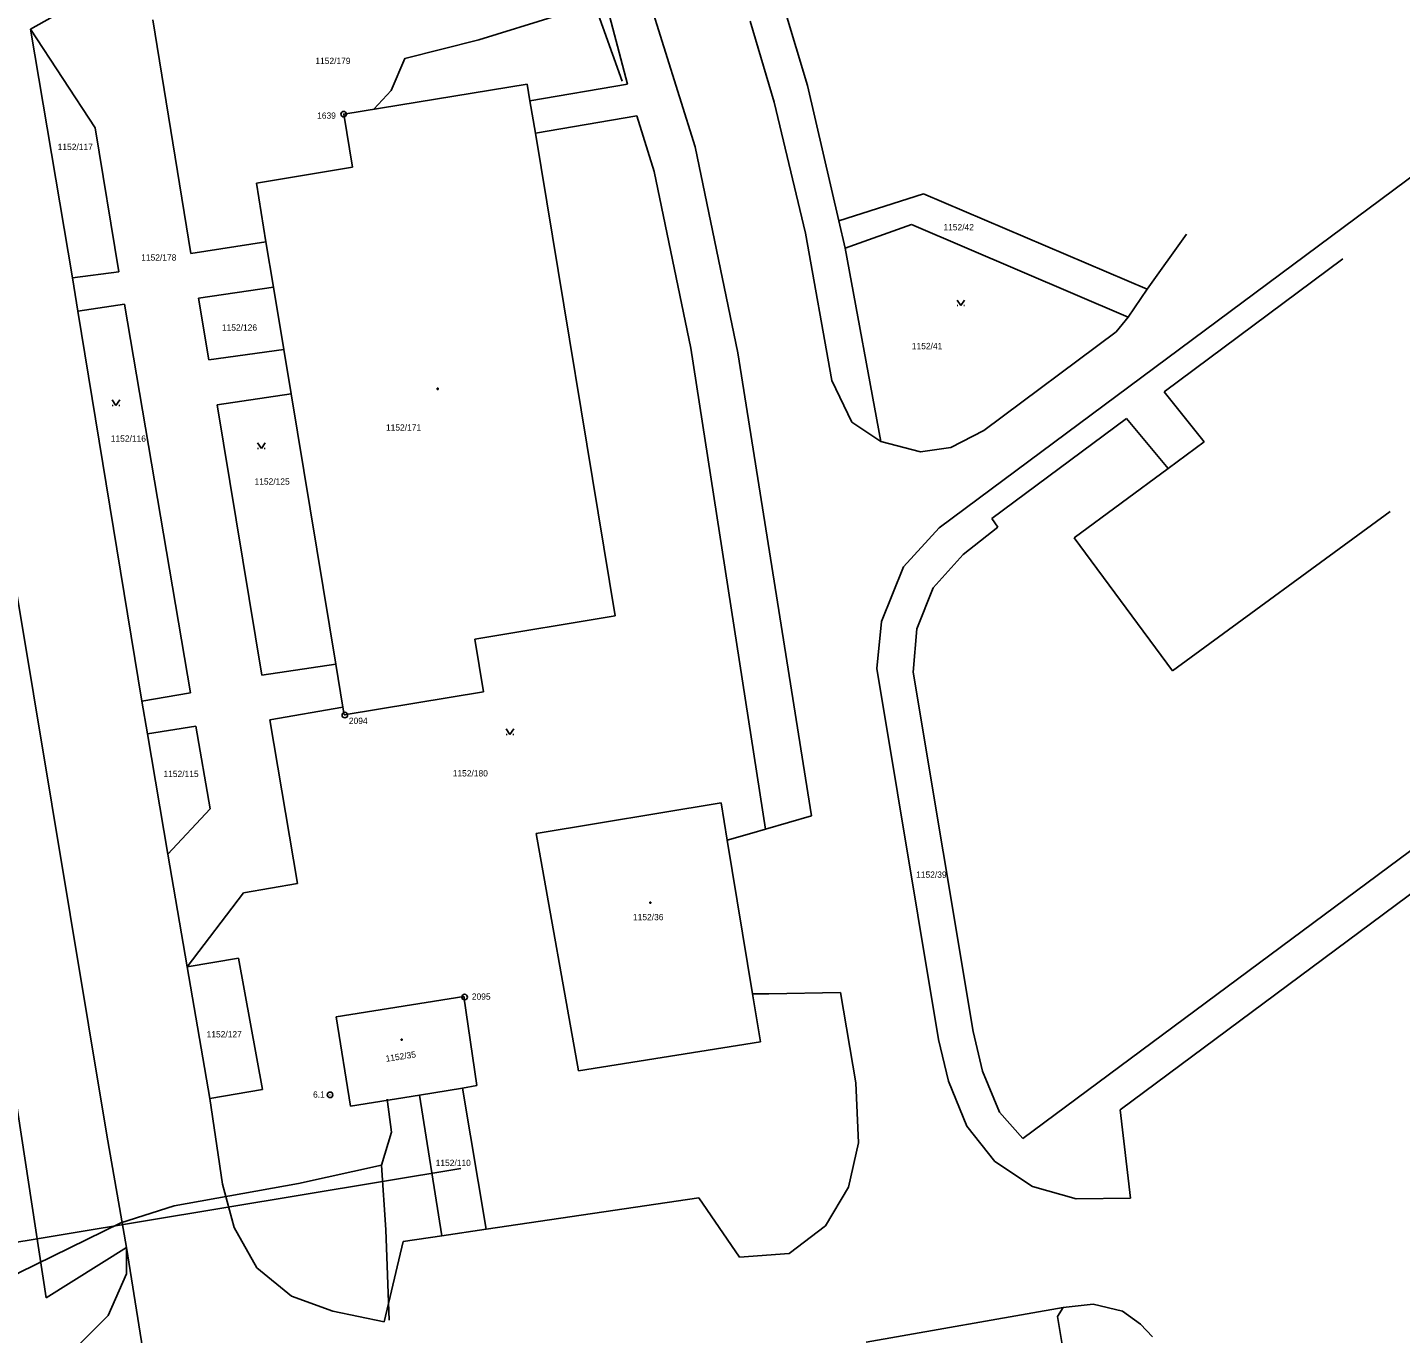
# Model space of a CAD drawing. Extents: x -609709 to -609357, y -1051535 to -1051131.
# Drawn here: x -609496.9 to -609404.3, y -1051388.6 to -1051300.6 of the extents above; entities that cross this region are included whole.
import ezdxf

# ---------------------------------------------------------------- set-up
doc = ezdxf.new("R2010")
doc.units = 0
for name, color, linetype in [('Vrstva 10', 7, 'Continuous'), ('Vrstva 12', 7, 'Continuous'), ('Vrstva 15', 7, 'Continuous')]:
    doc.layers.add(name, color=color, linetype=linetype)

msp = doc.modelspace()

# ---------------------------------------------------------------- linework, layer by layer
at = {"layer": 'Vrstva 10'}
for p, q in [((-609432.83, -1051332.32), (-609357.01, -1051275.97)), ((-609458.85, -1051295.32), (-609456.45, -1051304.37)), ((-609496.71, -1051300.67), (-609492.16, -1051298.11)), ((-609455.21, -1051298.05), (-609451.89, -1051308.61)), ((-609445.86, -1051299.39), (-609444.32, -1051304.46)), ((-609488.45, -1051300.05), (-609485.89, -1051315.79)), ((-609448.19, -1051300.13), (-609446.56, -1051305.59)), ((-609496.71, -1051300.67), (-609492.35, -1051307.31)), ((-609496.71, -1051300.67), (-609493.88, -1051317.44)), ((-609475.59, -1051306.4), (-609463.22, -1051304.37)), ((-609463.22, -1051304.37), (-609463.04, -1051305.49)), ((-609463.04, -1051305.49), (-609456.45, -1051304.37)), ((-609444.32, -1051304.46), (-609442.21, -1051313.59)), ((-609463.04, -1051305.49), (-609462.67, -1051307.68)), ((-609446.56, -1051305.59), (-609444.46, -1051314.42)), ((-609475.59, -1051306.4), (-609474.99, -1051309.98)), ((-609462.67, -1051307.68), (-609455.83, -1051306.52)), ((-609455.83, -1051306.52), (-609454.65, -1051310.27)), ((-609492.35, -1051307.31), (-609490.75, -1051317.02)), ((-609462.67, -1051307.68), (-609457.3, -1051340.22)), ((-609451.89, -1051308.61), (-609449.03, -1051322.49)), ((-609462.37, -1051309.5), (-609462.37, -1051309.5)), ((-609481.47, -1051311.06), (-609474.99, -1051309.98)), ((-609454.65, -1051310.27), (-609452.19, -1051322.16)), ((-609481.47, -1051311.06), (-609480.83, -1051315.01)), ((-609454.28, -1051312.05), (-609454.28, -1051312.05)), ((-609442.21, -1051313.59), (-609436.51, -1051311.76)), ((-609436.51, -1051311.76), (-609421.42, -1051318.19)), ((-609453.88, -1051314.01), (-609453.88, -1051314.01)), ((-609442.21, -1051313.59), (-609441.79, -1051315.42)), ((-609441.79, -1051315.42), (-609437.31, -1051313.84)), ((-609437.31, -1051313.84), (-609422.7, -1051320.08)), ((-609485.89, -1051315.79), (-609480.83, -1051315.01)), ((-609480.83, -1051315.01), (-609480.32, -1051318.07)), ((-609444.46, -1051314.42), (-609442.68, -1051324.36)), ((-609421.42, -1051318.19), (-609418.77, -1051314.48)), ((-609441.79, -1051315.42), (-609439.38, -1051328.47)), ((-609420.29, -1051325.11), (-609408.23, -1051316.16)), ((-609493.88, -1051317.44), (-609490.75, -1051317.02)), ((-609493.88, -1051317.44), (-609493.51, -1051319.67)), ((-609485.37, -1051318.79), (-609480.32, -1051318.07)), ((-609480.32, -1051318.07), (-609479.63, -1051322.26)), ((-609485.37, -1051318.79), (-609484.67, -1051322.95)), ((-609434.23, -1051318.925), (-609433.98, -1051319.3)), ((-609433.98, -1051319.3), (-609433.73, -1051318.925)), ((-609422.7, -1051320.08), (-609421.42, -1051318.19)), ((-609493.51, -1051319.67), (-609490.37, -1051319.21)), ((-609493.51, -1051319.67), (-609489.19, -1051345.96)), ((-609490.37, -1051319.21), (-609485.92, -1051345.41)), ((-609434.23, -1051319.3), (-609434.18, -1051319.3)), ((-609433.78, -1051319.3), (-609433.73, -1051319.3)), ((-609505.79, -1051320.08), (-609495.64, -1051386.18)), ((-609423.51, -1051321.08), (-609422.7, -1051320.08)), ((-609432.44, -1051327.72), (-609423.51, -1051321.08)), ((-609500.39, -1051322.14), (-609491.56, -1051375.22)), ((-609484.67, -1051322.95), (-609479.63, -1051322.26)), ((-609479.63, -1051322.26), (-609479.14, -1051325.24)), ((-609452.19, -1051322.16), (-609447.16, -1051354.59)), ((-609449.03, -1051322.49), (-609444.06, -1051353.69)), ((-609442.68, -1051324.36), (-609441.33, -1051327.15)), ((-609484.13, -1051325.98), (-609479.14, -1051325.24)), ((-609479.14, -1051325.24), (-609476.12, -1051343.46)), ((-609469.295, -1051324.875), (-609469.22, -1051324.875)), ((-609469.295, -1051324.95), (-609469.295, -1051324.875)), ((-609469.22, -1051324.95), (-609469.295, -1051324.95)), ((-609469.22, -1051324.875), (-609469.22, -1051324.95)), ((-609420.29, -1051325.11), (-609417.58, -1051328.48)), ((-609491.19, -1051325.655), (-609490.94, -1051326.03)), ((-609491.19, -1051326.03), (-609491.14, -1051326.03)), ((-609490.94, -1051326.03), (-609490.69, -1051325.655)), ((-609490.74, -1051326.03), (-609490.69, -1051326.03)), ((-609484.13, -1051325.98), (-609481.1, -1051344.21)), ((-609441.33, -1051327.15), (-609439.38, -1051328.47)), ((-609431.9, -1051333.65), (-609422.81, -1051326.91)), ((-609422.81, -1051326.91), (-609420.02, -1051330.28)), ((-609434.66, -1051328.87), (-609432.44, -1051327.72)), ((-609481.39, -1051328.555), (-609481.14, -1051328.93)), ((-609481.39, -1051328.93), (-609481.34, -1051328.93)), ((-609481.14, -1051328.93), (-609480.89, -1051328.555)), ((-609480.94, -1051328.93), (-609480.89, -1051328.93)), ((-609439.38, -1051328.47), (-609436.7, -1051329.15)), ((-609436.7, -1051329.15), (-609434.66, -1051328.87)), ((-609420.02, -1051330.28), (-609417.58, -1051328.48)), ((-609426.34, -1051334.95), (-609420.02, -1051330.28)), ((-609435.44, -1051334.29), (-609432.83, -1051332.32)), ((-609431.9, -1051333.65), (-609431.49, -1051334.23)), ((-609419.71, -1051343.92), (-609405.05, -1051333.17)), ((-609437.86, -1051336.91), (-609435.44, -1051334.29)), ((-609433.83, -1051336.07), (-609431.49, -1051334.23)), ((-609426.34, -1051334.95), (-609419.71, -1051343.92)), ((-609435.85, -1051338.32), (-609433.83, -1051336.07)), ((-609439.34, -1051340.59), (-609437.86, -1051336.91)), ((-609436.96, -1051341.09), (-609435.85, -1051338.32)), ((-609466.75, -1051341.79), (-609457.3, -1051340.22)), ((-609439.66, -1051343.77), (-609439.34, -1051340.59)), ((-609437.2, -1051344.02), (-609436.96, -1051341.09)), ((-609466.75, -1051341.79), (-609466.17, -1051345.34)), ((-609429.8, -1051375.44), (-609383.99, -1051341.41)), ((-609481.1, -1051344.21), (-609476.12, -1051343.46)), ((-609476.12, -1051343.46), (-609475.64, -1051346.37)), ((-609439.66, -1051343.77), (-609435.49, -1051368.77)), ((-609423.24, -1051373.5), (-609382.56, -1051343.27)), ((-609437.2, -1051344.02), (-609433.16, -1051368.24)), ((-609489.19, -1051345.96), (-609485.92, -1051345.41)), ((-609475.56, -1051346.89), (-609466.17, -1051345.34)), ((-609489.19, -1051345.96), (-609488.82, -1051348.17)), ((-609480.56, -1051347.23), (-609475.64, -1051346.37)), ((-609475.64, -1051346.37), (-609475.56, -1051346.89)), ((-609488.82, -1051348.17), (-609485.55, -1051347.65)), ((-609485.55, -1051347.65), (-609484.6, -1051353.23)), ((-609480.56, -1051347.23), (-609478.71, -1051358.25)), ((-609488.82, -1051348.17), (-609487.44, -1051356.28)), ((-609464.63, -1051347.825), (-609464.38, -1051348.2)), ((-609464.63, -1051348.2), (-609464.58, -1051348.2)), ((-609464.38, -1051348.2), (-609464.13, -1051347.825)), ((-609464.18, -1051348.2), (-609464.13, -1051348.2)), ((-609487.44, -1051356.28), (-609484.6, -1051353.23)), ((-609462.61, -1051354.88), (-609450.15, -1051352.81)), ((-609450.15, -1051352.81), (-609449.73, -1051355.34)), ((-609447.16, -1051354.59), (-609444.06, -1051353.69)), ((-609462.61, -1051354.88), (-609459.76, -1051370.89)), ((-609449.73, -1051355.34), (-609448.07, -1051354.86)), ((-609448.07, -1051354.86), (-609447.16, -1051354.59)), ((-609449.73, -1051355.34), (-609448.03, -1051365.7)), ((-609487.44, -1051356.28), (-609486.14, -1051363.88)), ((-609482.35, -1051358.88), (-609478.71, -1051358.25)), ((-609486.14, -1051363.88), (-609482.35, -1051358.88)), ((-609454.955, -1051359.505), (-609454.88, -1051359.505)), ((-609454.955, -1051359.58), (-609454.955, -1051359.505)), ((-609454.88, -1051359.58), (-609454.955, -1051359.58)), ((-609454.88, -1051359.505), (-609454.88, -1051359.58)), ((-609486.14, -1051363.88), (-609482.69, -1051363.29)), ((-609482.69, -1051363.29), (-609481.07, -1051372.14)), ((-609486.14, -1051363.88), (-609484.62, -1051372.75)), ((-609476.09, -1051367.23), (-609467.49, -1051365.86)), ((-609467.49, -1051365.86), (-609466.61, -1051371.88)), ((-609448.03, -1051365.7), (-609446.93, -1051365.68)), ((-609448.03, -1051365.7), (-609447.5, -1051368.92)), ((-609446.93, -1051365.68), (-609442.09, -1051365.6)), ((-609442.09, -1051365.6), (-609441.07, -1051371.69)), ((-609476.09, -1051367.23), (-609475.13, -1051373.26)), ((-609471.72, -1051368.745), (-609471.645, -1051368.745)), ((-609471.72, -1051368.82), (-609471.72, -1051368.745)), ((-609471.645, -1051368.82), (-609471.72, -1051368.82)), ((-609471.645, -1051368.745), (-609471.645, -1051368.82)), ((-609459.76, -1051370.89), (-609447.5, -1051368.92)), ((-609435.49, -1051368.77), (-609434.83, -1051371.58)), ((-609433.16, -1051368.24), (-609432.53, -1051370.9)), ((-609441.07, -1051371.69), (-609440.88, -1051375.74)), ((-609434.83, -1051371.58), (-609433.58, -1051374.6)), ((-609432.53, -1051370.9), (-609431.38, -1051373.66)), ((-609484.62, -1051372.75), (-609481.07, -1051372.14)), ((-609475.13, -1051373.26), (-609470.48, -1051372.51)), ((-609470.48, -1051372.51), (-609467.58, -1051372.04)), ((-609470.48, -1051372.51), (-609468.97, -1051382)), ((-609467.58, -1051372.04), (-609466.61, -1051371.88)), ((-609467.58, -1051372.04), (-609465.99, -1051381.56)), ((-609484.62, -1051372.75), (-609483.77, -1051378.51)), ((-609423.24, -1051373.5), (-609422.55, -1051379.46)), ((-609431.38, -1051373.66), (-609429.8, -1051375.44)), ((-609491.56, -1051375.22), (-609490.24, -1051382.78)), ((-609433.58, -1051374.6), (-609431.7, -1051376.99)), ((-609441.56, -1051378.72), (-609440.88, -1051375.74)), ((-609431.7, -1051376.99), (-609429.15, -1051378.68)), ((-609483.77, -1051378.51), (-609482.98, -1051381.45)), ((-609443.12, -1051381.33), (-609441.56, -1051378.72)), ((-609429.15, -1051378.68), (-609426.21, -1051379.5)), ((-609465.99, -1051381.56), (-609451.66, -1051379.45)), ((-609451.66, -1051379.45), (-609448.91, -1051383.44)), ((-609426.21, -1051379.5), (-609422.55, -1051379.46)), ((-609482.98, -1051381.45), (-609481.45, -1051384.15)), ((-609468.97, -1051382), (-609465.99, -1051381.56)), ((-609445.56, -1051383.19), (-609443.12, -1051381.33)), ((-609495.64, -1051386.18), (-609490.24, -1051382.78)), ((-609490.24, -1051382.78), (-609490.23, -1051384.57)), ((-609490.24, -1051382.78), (-609487.04, -1051402.58)), ((-609472.86, -1051387.81), (-609471.58, -1051382.38)), ((-609471.58, -1051382.38), (-609468.97, -1051382)), ((-609448.91, -1051383.44), (-609445.56, -1051383.19)), ((-609491.46, -1051387.37), (-609490.23, -1051384.57)), ((-609481.45, -1051384.15), (-609479.1, -1051386.08)), ((-609479.1, -1051386.08), (-609476.33, -1051387.08)), ((-609493.63, -1051389.53), (-609491.46, -1051387.37)), ((-609476.33, -1051387.08), (-609472.86, -1051387.81)), ((-609440.36, -1051389.16), (-609427.08, -1051386.84)), ((-609427.08, -1051386.84), (-609427.46, -1051387.44)), ((-609427.46, -1051387.44), (-609426.8, -1051391.39)), ((-609427.08, -1051386.84), (-609425.07, -1051386.6)), ((-609425.07, -1051386.6), (-609423.1, -1051387.07)), ((-609423.1, -1051387.07), (-609421.88, -1051387.95)), ((-609421.88, -1051387.95), (-609421.07, -1051388.81))]:
    msp.add_line(p, q, dxfattribs=at)
for centre, radius in [((-609475.59, -1051306.4), 0.188), ((-609475.59, -1051306.4), 0.0025), ((-609475.51, -1051346.9), 0.188), ((-609475.51, -1051346.9), 0.0025), ((-609467.44, -1051365.91), 0.188), ((-609467.44, -1051365.91), 0.0025), ((-609476.51, -1051372.5), 0.188), ((-609476.51, -1051372.5), 0.0025)]:
    msp.add_circle(centre, radius, dxfattribs=at)
at = {"layer": 'Vrstva 12'}
for points in [[(-609615.546, -1051325.052), (-609614.108, -1051326.974), (-609589.099, -1051308.266), (-609582.815, -1051303.565), (-609514.844, -1051393.856), (-609499.807, -1051382.785), (-609467.693, -1051377.467)], [(-609513.99, -1051396.17), (-609509.03, -1051392.84), (-609504.6, -1051389.36), (-609497.48, -1051384.5), (-609490.61, -1051381.13), (-609487.01, -1051379.99), (-609478.64, -1051378.48), (-609473.03, -1051377.23), (-609472.37, -1051375.01), (-609472.654, -1051372.8)], [(-609473.03, -1051377.23), (-609472.76, -1051381.59), (-609472.52, -1051387.69)]]:
    msp.add_lwpolyline(points, dxfattribs=at)
at = {"layer": 'Vrstva 15'}
for points in [[(-609494.99, -1051250.43), (-609494.01, -1051253.14), (-609491.16, -1051257.62), (-609488.26, -1051261.12), (-609484.58, -1051266.44), (-609477.4, -1051277.58), (-609471.72, -1051282.43), (-609466.9, -1051283.75), (-609463.63, -1051287.54), (-609462.49, -1051293.69), (-609459.257, -1051298.042), (-609461.25, -1051299.78), (-609466.49, -1051301.38), (-609471.47, -1051302.65), (-609472.4, -1051304.8), (-609473.562, -1051306.057)], [(-609459.257, -1051298.042), (-609458.77, -1051298.7), (-609456.82, -1051304.18)]]:
    msp.add_lwpolyline(points, dxfattribs=at)

# ---------------------------------------------------------------- texts
at = {"layer": 'Vrstva 10'}
for s, p in [('1152/179', (-609477.5, -1051303.02)), ('1639', (-609477.38, -1051306.71)), ('1152/117', (-609494.87, -1051308.82)), ('1152/42', (-609435.16, -1051314.23)), ('1152/178', (-609489.24, -1051316.27)), ('1152/126', (-609483.8, -1051320.99)), ('1152/41', (-609437.29, -1051322.24)), ('1152/171', (-609472.74, -1051327.73)), ('1152/116', (-609491.29, -1051328.48)), ('1152/125', (-609481.6, -1051331.37)), ('2094', (-609475.24, -1051347.5)), ('1152/115', (-609487.74, -1051351.08)), ('1152/180', (-609468.24, -1051351.04)), ('1152/39', (-609437, -1051357.87)), ('1152/36', (-609456.09, -1051360.73)), ('2095', (-609466.95, -1051366.09)), ('1152/127', (-609484.83, -1051368.63)), ('6.1', (-609477.657, -1051372.69)), ('1152/110', (-609469.39, -1051377.3))]:
    msp.add_text(s, height=0.425, dxfattribs=at).set_placement(p)
msp.add_text('1152/35', height=0.425, rotation=8.41464, dxfattribs=at).set_placement((-609472.728, -1051370.273))

doc.saveas('drawing.dxf')
